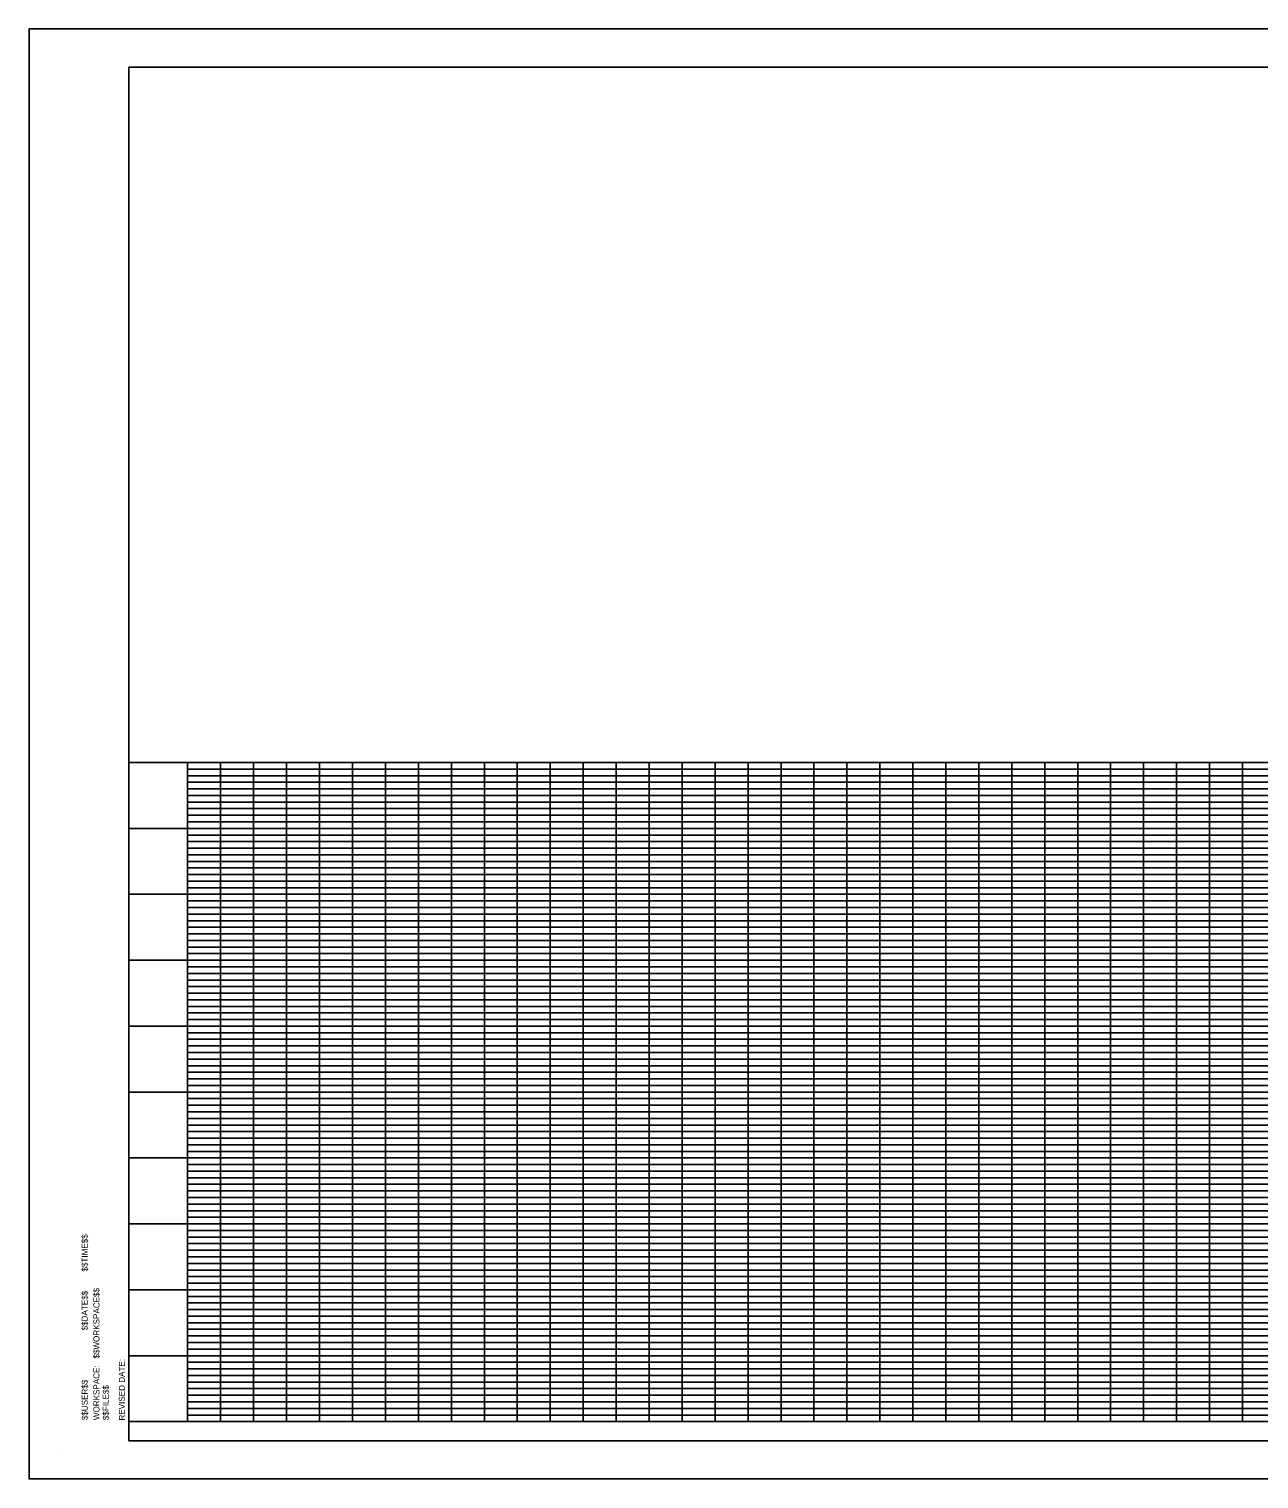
# Model space of a CAD drawing. Extents: x 759422 to 1402138, y 1662254 to 1956530.
# Drawn here: x 1400271 to 1401204, y 1955430 to 1956530 of the extents above; entities that cross this region are included whole.
import ezdxf

# ---------------------------------------------------------------- set-up
doc = ezdxf.new("R2010")
doc.units = 0
doc.layers.add('1', color=7, linetype='Continuous')

msp = doc.modelspace()

# ---------------------------------------------------------------- linework, layer by layer
at = {"layer": '1'}
for p, q in [((1400347.1, 1956501.5), (1401942.4, 1956501.5)), ((1400347.1, 1955459.2), (1400347.1, 1956501.5)), ((1401942.4, 1955973.9), (1400347.1, 1955973.9)), ((1400391.6, 1955473.9), (1400391.6, 1955973.9)), ((1401891.6, 1955968.9), (1400391.6, 1955968.9)), ((1400416.6, 1955473.9), (1400416.6, 1955973.9)), ((1400441.6, 1955473.9), (1400441.6, 1955973.9)), ((1400466.6, 1955473.9), (1400466.6, 1955973.9)), ((1400491.6, 1955473.9), (1400491.6, 1955973.9)), ((1400516.6, 1955473.9), (1400516.6, 1955973.9)), ((1400541.6, 1955473.9), (1400541.6, 1955973.9)), ((1400566.6, 1955473.9), (1400566.6, 1955973.9)), ((1400591.6, 1955473.9), (1400591.6, 1955973.9)), ((1400616.6, 1955473.9), (1400616.6, 1955973.9)), ((1400641.6, 1955473.9), (1400641.6, 1955973.9)), ((1400666.6, 1955473.9), (1400666.6, 1955973.9)), ((1400691.6, 1955473.9), (1400691.6, 1955973.9)), ((1400716.6, 1955473.9), (1400716.6, 1955973.9)), ((1400741.6, 1955473.9), (1400741.6, 1955973.9)), ((1400766.6, 1955473.9), (1400766.6, 1955973.9)), ((1400791.6, 1955473.9), (1400791.6, 1955973.9)), ((1400816.6, 1955473.9), (1400816.6, 1955973.9)), ((1400841.6, 1955473.9), (1400841.6, 1955973.9)), ((1400866.6, 1955473.9), (1400866.6, 1955973.9)), ((1400891.6, 1955473.9), (1400891.6, 1955973.9)), ((1400916.6, 1955473.9), (1400916.6, 1955973.9)), ((1400941.6, 1955473.9), (1400941.6, 1955973.9)), ((1400966.6, 1955473.9), (1400966.6, 1955973.9)), ((1400991.6, 1955473.9), (1400991.6, 1955973.9)), ((1401016.6, 1955473.9), (1401016.6, 1955973.9)), ((1401041.6, 1955473.9), (1401041.6, 1955973.9)), ((1401066.6, 1955473.9), (1401066.6, 1955973.9)), ((1401091.6, 1955473.9), (1401091.6, 1955973.9)), ((1401116.6, 1955473.9), (1401116.6, 1955973.9)), ((1401141.6, 1955473.9), (1401141.6, 1955973.9)), ((1401166.6, 1955473.9), (1401166.6, 1955973.9)), ((1401191.6, 1955473.9), (1401191.6, 1955973.9)), ((1401891.6, 1955963.9), (1400391.6, 1955963.9)), ((1401891.6, 1955958.9), (1400391.6, 1955958.9)), ((1401891.6, 1955953.9), (1400391.6, 1955953.9)), ((1401891.6, 1955948.9), (1400391.6, 1955948.9)), ((1401891.6, 1955943.9), (1400391.6, 1955943.9)), ((1401891.6, 1955938.9), (1400391.6, 1955938.9)), ((1401891.6, 1955933.9), (1400391.6, 1955933.9)), ((1401942.4, 1955923.9), (1400347.1, 1955923.9)), ((1401891.6, 1955928.9), (1400391.6, 1955928.9)), ((1401891.6, 1955918.9), (1400391.6, 1955918.9)), ((1401891.6, 1955913.9), (1400391.6, 1955913.9)), ((1401891.6, 1955908.9), (1400391.6, 1955908.9)), ((1401891.6, 1955903.9), (1400391.6, 1955903.9)), ((1401891.6, 1955898.9), (1400391.6, 1955898.9)), ((1401891.6, 1955893.9), (1400391.6, 1955893.9)), ((1401891.6, 1955888.9), (1400391.6, 1955888.9)), ((1401891.6, 1955883.9), (1400391.6, 1955883.9)), ((1401891.6, 1955878.9), (1400391.6, 1955878.9)), ((1401942.4, 1955873.9), (1400347.1, 1955873.9)), ((1401891.6, 1955868.9), (1400391.6, 1955868.9)), ((1401891.6, 1955863.9), (1400391.6, 1955863.9)), ((1401891.6, 1955858.9), (1400391.6, 1955858.9)), ((1401891.6, 1955853.9), (1400391.6, 1955853.9)), ((1401891.6, 1955848.9), (1400391.6, 1955848.9)), ((1401891.6, 1955843.9), (1400391.6, 1955843.9)), ((1401891.6, 1955838.9), (1400391.6, 1955838.9)), ((1401891.6, 1955833.9), (1400391.6, 1955833.9)), ((1401942.4, 1955823.9), (1400347.1, 1955823.9)), ((1401891.6, 1955828.9), (1400391.6, 1955828.9)), ((1401891.6, 1955818.9), (1400391.6, 1955818.9)), ((1401891.6, 1955813.9), (1400391.6, 1955813.9)), ((1401891.6, 1955808.9), (1400391.6, 1955808.9)), ((1401891.6, 1955803.9), (1400391.6, 1955803.9)), ((1401891.6, 1955798.9), (1400391.6, 1955798.9)), ((1401891.6, 1955793.9), (1400391.6, 1955793.9)), ((1401891.6, 1955788.9), (1400391.6, 1955788.9)), ((1401891.6, 1955783.9), (1400391.6, 1955783.9)), ((1401891.6, 1955778.9), (1400391.6, 1955778.9)), ((1401942.4, 1955773.9), (1400347.1, 1955773.9)), ((1401891.6, 1955768.9), (1400391.6, 1955768.9)), ((1401891.6, 1955763.9), (1400391.6, 1955763.9)), ((1401891.6, 1955758.9), (1400391.6, 1955758.9)), ((1401891.6, 1955753.9), (1400391.6, 1955753.9)), ((1401891.6, 1955748.9), (1400391.6, 1955748.9)), ((1401891.6, 1955743.9), (1400391.6, 1955743.9)), ((1401891.6, 1955738.9), (1400391.6, 1955738.9)), ((1401942.4, 1955723.9), (1400347.1, 1955723.9)), ((1401891.6, 1955733.9), (1400391.6, 1955733.9)), ((1401891.6, 1955728.9), (1400391.6, 1955728.9)), ((1401891.6, 1955718.9), (1400391.6, 1955718.9)), ((1401891.6, 1955713.9), (1400391.6, 1955713.9)), ((1401891.6, 1955708.9), (1400391.6, 1955708.9)), ((1401891.6, 1955703.9), (1400391.6, 1955703.9)), ((1401891.6, 1955698.9), (1400391.6, 1955698.9)), ((1401891.6, 1955693.9), (1400391.6, 1955693.9)), ((1401891.6, 1955688.9), (1400391.6, 1955688.9)), ((1401891.6, 1955683.9), (1400391.6, 1955683.9)), ((1401942.4, 1955673.9), (1400347.1, 1955673.9)), ((1401891.6, 1955678.9), (1400391.6, 1955678.9)), ((1401891.6, 1955668.9), (1400391.6, 1955668.9)), ((1401891.6, 1955663.9), (1400391.6, 1955663.9)), ((1401891.6, 1955658.9), (1400391.6, 1955658.9)), ((1401891.6, 1955653.9), (1400391.6, 1955653.9)), ((1401891.6, 1955648.9), (1400391.6, 1955648.9)), ((1401891.6, 1955643.9), (1400391.6, 1955643.9)), ((1401891.6, 1955638.9), (1400391.6, 1955638.9)), ((1401891.6, 1955633.9), (1400391.6, 1955633.9)), ((1401891.6, 1955628.9), (1400391.6, 1955628.9)), ((1401942.4, 1955623.9), (1400347.1, 1955623.9)), ((1401891.6, 1955618.9), (1400391.6, 1955618.9)), ((1401891.6, 1955613.9), (1400391.6, 1955613.9)), ((1401891.6, 1955608.9), (1400391.6, 1955608.9)), ((1401891.6, 1955603.9), (1400391.6, 1955603.9)), ((1401891.6, 1955598.9), (1400391.6, 1955598.9)), ((1401891.6, 1955593.9), (1400391.6, 1955593.9)), ((1401891.6, 1955588.9), (1400391.6, 1955588.9)), ((1401891.6, 1955583.9), (1400391.6, 1955583.9)), ((1401942.4, 1955573.9), (1400347.1, 1955573.9)), ((1401891.6, 1955578.9), (1400391.6, 1955578.9)), ((1401891.6, 1955568.9), (1400391.6, 1955568.9)), ((1401891.6, 1955563.9), (1400391.6, 1955563.9)), ((1401891.6, 1955558.9), (1400391.6, 1955558.9)), ((1401891.6, 1955553.9), (1400391.6, 1955553.9)), ((1401891.6, 1955548.9), (1400391.6, 1955548.9)), ((1401891.6, 1955543.9), (1400391.6, 1955543.9)), ((1401891.6, 1955538.9), (1400391.6, 1955538.9)), ((1401891.6, 1955533.9), (1400391.6, 1955533.9)), ((1401891.6, 1955528.9), (1400391.6, 1955528.9)), ((1401942.4, 1955523.9), (1400347.1, 1955523.9)), ((1401891.6, 1955518.9), (1400391.6, 1955518.9)), ((1401891.6, 1955513.9), (1400391.6, 1955513.9)), ((1401891.6, 1955508.9), (1400391.6, 1955508.9)), ((1401891.6, 1955503.9), (1400391.6, 1955503.9)), ((1401891.6, 1955498.9), (1400391.6, 1955498.9)), ((1401891.6, 1955493.9), (1400391.6, 1955493.9)), ((1401891.6, 1955488.9), (1400391.6, 1955488.9)), ((1401891.6, 1955483.9), (1400391.6, 1955483.9)), ((1401942.4, 1955473.9), (1400347.1, 1955473.9)), ((1401891.6, 1955478.9), (1400391.6, 1955478.9)), ((1401942.4, 1955459.2), (1400347.1, 1955459.2)), ((1400294.7, 1955451.8), (1400294.7, 1955451.8))]:
    msp.add_line(p, q, dxfattribs=at)
msp.add_lwpolyline([(1401971.3, 1956530.4), (1400271.3, 1956530.4), (1400271.3, 1955430.4), (1401971.3, 1955430.4)], close=True, dxfattribs=at)

# ---------------------------------------------------------------- texts
for s, p in [('$$TIME$$', (1400315.8, 1955587.7)), ('$$DATE$$', (1400315.8, 1955543.1)), ('$$WORKSPACE$$', (1400324.7, 1955521.7)), ('WORKSPACE:', (1400324.7, 1955475)), ('REVISED DATE:', (1400344, 1955474.7)), ('$$USER$$', (1400315.8, 1955475)), ('$$FILE$$', (1400331.8, 1955475))]:
    msp.add_text(s, height=4.59, rotation=90, dxfattribs=at).set_placement(p)

doc.saveas('drawing.dxf')
